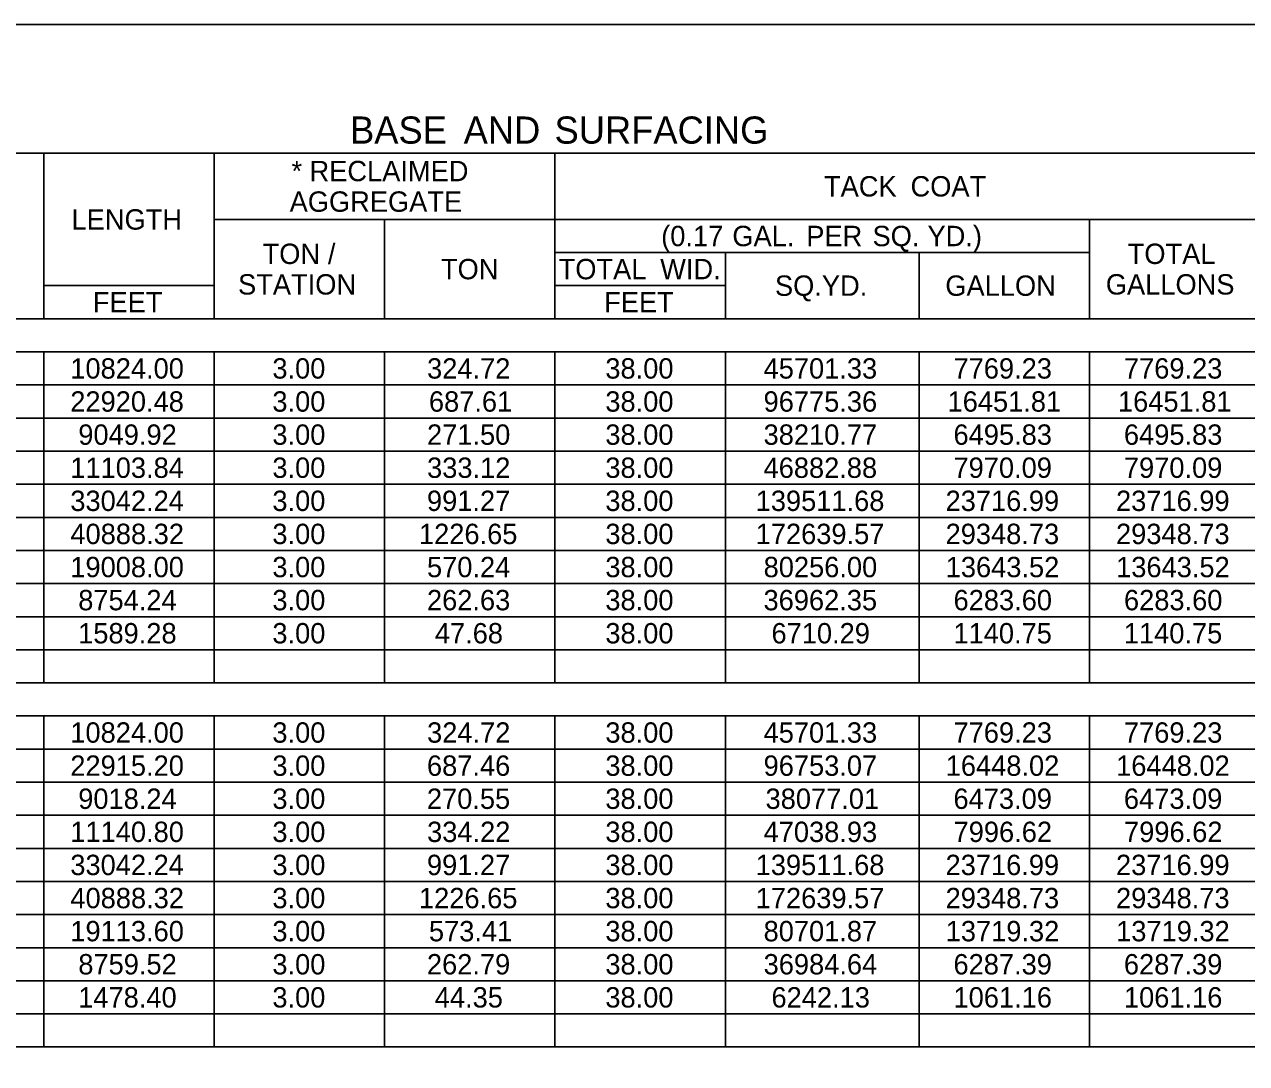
# Model space of a CAD drawing. Extents: x 2261867 to 2275370, y -3124789 to -3122260.
# Drawn here: x 2269764 to 2270088.1, y -3123898.7 to -3123623.2 of the extents above; entities that cross this region are included whole.
import ezdxf

# ---------------------------------------------------------------- set-up
doc = ezdxf.new("R2010")
doc.units = 0
doc.layers.add('Default', color=7, linetype='Continuous')
doc.layers.add('DSN_DRFT_Named-Boundary', color=7, linetype='Continuous')

msp = doc.modelspace()

# ---------------------------------------------------------------- linework, layer by layer
at = {"layer": 'Default'}
for p, q in [((2269400.16, -3123657.37), (2270414.11, -3123657.37)), ((2269769.15, -3123701.24), (2269769.15, -3123657.37)), ((2269814.34, -3123701.24), (2269814.34, -3123657.37)), ((2269904.72, -3123701.24), (2269904.72, -3123657.37)), ((2269814.34, -3123674.92), (2270414.11, -3123674.92)), ((2269859.53, -3123701.24), (2269859.53, -3123674.92)), ((2270046.44, -3123701.24), (2270046.44, -3123674.92)), ((2269904.72, -3123683.69), (2270046.44, -3123683.69)), ((2269949.92, -3123701.24), (2269949.92, -3123683.69)), ((2270001.25, -3123701.24), (2270001.25, -3123683.69)), ((2269769.15, -3123692.47), (2269814.34, -3123692.47)), ((2269814.34, -3123701.24), (2269814.34, -3123692.47)), ((2269904.72, -3123692.47), (2269949.92, -3123692.47)), ((2269949.92, -3123701.24), (2269949.92, -3123692.47)), ((2269400.16, -3123701.24), (2270414.11, -3123701.24)), ((2269814.34, -3123701.24), (2269949.92, -3123701.24)), ((2269949.92, -3123701.24), (2270001.25, -3123701.24)), ((2270001.25, -3123701.24), (2270136.82, -3123701.24)), ((2269400.16, -3123710.02), (2270414.11, -3123710.02)), ((2269769.15, -3123797.77), (2269769.15, -3123710.02)), ((2269769.15, -3123797.77), (2269769.15, -3123710.02)), ((2269814.34, -3123797.77), (2269814.34, -3123710.02)), ((2269814.34, -3123797.77), (2269814.34, -3123710.02)), ((2269859.53, -3123797.77), (2269859.53, -3123710.02)), ((2269859.53, -3123797.77), (2269859.53, -3123710.02)), ((2269904.72, -3123797.77), (2269904.72, -3123710.02)), ((2269904.72, -3123797.77), (2269904.72, -3123710.02)), ((2269949.92, -3123797.77), (2269949.92, -3123710.02)), ((2269949.92, -3123797.77), (2269949.92, -3123710.02)), ((2270001.25, -3123797.77), (2270001.25, -3123710.02)), ((2270001.25, -3123797.77), (2270001.25, -3123710.02)), ((2270046.44, -3123797.77), (2270046.44, -3123710.02)), ((2270046.44, -3123797.77), (2270046.44, -3123710.02)), ((2269400.16, -3123718.79), (2270414.11, -3123718.79)), ((2269400.16, -3123727.57), (2270414.11, -3123727.57)), ((2269400.16, -3123736.34), (2270414.11, -3123736.34)), ((2269400.16, -3123745.12), (2270414.11, -3123745.12)), ((2269400.16, -3123753.89), (2270414.11, -3123753.89)), ((2269400.16, -3123762.67), (2270414.11, -3123762.67)), ((2269400.16, -3123771.44), (2270414.11, -3123771.44)), ((2269400.16, -3123780.22), (2270414.11, -3123780.22)), ((2269400.16, -3123788.99), (2270414.11, -3123788.99)), ((2269400.16, -3123797.77), (2270414.11, -3123797.77)), ((2269400.16, -3123797.77), (2270414.11, -3123797.77)), ((2269400.16, -3123806.54), (2270414.11, -3123806.54)), ((2269769.15, -3123894.29), (2269769.15, -3123806.54)), ((2269769.15, -3123894.29), (2269769.15, -3123806.54)), ((2269814.34, -3123894.29), (2269814.34, -3123806.54)), ((2269814.34, -3123894.29), (2269814.34, -3123806.54)), ((2269859.53, -3123894.29), (2269859.53, -3123806.54)), ((2269859.53, -3123894.29), (2269859.53, -3123806.54)), ((2269904.72, -3123894.29), (2269904.72, -3123806.54)), ((2269904.72, -3123894.29), (2269904.72, -3123806.54)), ((2269949.92, -3123894.29), (2269949.92, -3123806.54)), ((2269949.92, -3123894.29), (2269949.92, -3123806.54)), ((2270001.25, -3123894.29), (2270001.25, -3123806.54)), ((2270001.25, -3123894.29), (2270001.25, -3123806.54)), ((2270046.44, -3123894.29), (2270046.44, -3123806.54)), ((2270046.44, -3123894.29), (2270046.44, -3123806.54)), ((2269400.16, -3123815.32), (2270414.11, -3123815.32)), ((2269400.16, -3123824.09), (2270414.11, -3123824.09)), ((2269400.16, -3123832.87), (2270414.11, -3123832.87)), ((2269400.16, -3123841.64), (2270414.11, -3123841.64)), ((2269400.16, -3123850.42), (2270414.11, -3123850.42)), ((2269400.16, -3123859.19), (2270414.11, -3123859.19)), ((2269400.16, -3123867.97), (2270414.11, -3123867.97)), ((2269400.16, -3123876.74), (2270414.11, -3123876.74)), ((2269400.16, -3123885.52), (2270414.11, -3123885.52)), ((2269400.16, -3123894.29), (2270414.11, -3123894.29)), ((2269400.16, -3123894.29), (2270414.11, -3123894.29))]:
    msp.add_line(p, q, dxfattribs=at)
at = {"layer": 'DSN_DRFT_Named-Boundary'}
msp.add_lwpolyline([(2269094.64, -3124789.38), (2270719.64, -3124789.38), (2270719.64, -3123623.23), (2269094.64, -3123623.23)], close=True, dxfattribs=at)

# ---------------------------------------------------------------- texts
at = {"layer": 'Default'}
for s, height, p in [('BASE', 7.2, (2269850.37, -3123654.83)), (' AND', 7.2, (2269877.82, -3123654.83)), (' SURFACING', 7.2, (2269901.92, -3123654.83)), ('*', 5.4, (2269834.86, -3123664.79)), (' RECLAIMED', 5.4, (2269837.63, -3123664.79)), ('TACK', 5.4, (2269976.05, -3123668.84)), (' COAT', 5.4, (2269996.99, -3123668.84)), ('AGGREGATE', 5.4, (2269834.36, -3123672.89)), ('LENGTH', 5.4, (2269776.53, -3123677.62)), ('(0.17', 5.4, (2269932.88, -3123682.01)), (' GAL.', 5.4, (2269949.74, -3123682.01)), (' PER', 5.4, (2269969.34, -3123682.01)), (' SQ.', 5.4, (2269986.91, -3123682.01)), (' YD.)', 5.4, (2270001.49, -3123682.01)), ('TON', 5.4, (2269827.18, -3123686.73)), (' /', 5.4, (2269842.5, -3123686.73)), ('TOTAL', 5.4, (2270056.58, -3123686.73)), ('TON', 5.4, (2269874.47, -3123690.78)), ('TOTAL', 5.4, (2269905.69, -3123690.78)), (' WID.', 5.4, (2269930.61, -3123690.78)), ('STATION', 5.4, (2269820.68, -3123694.83)), ('SQ.YD.', 5.4, (2269963.05, -3123695.17)), ('GALLON', 5.4, (2270008.22, -3123695.17)), ('GALLONS', 5.4, (2270050.78, -3123694.83)), ('FEET', 5.4, (2269782.18, -3123699.56)), ('FEET', 5.4, (2269917.75, -3123699.56)), ('10824.00', 5.4, (2269776.2, -3123717.11)), ('3.00', 5.4, (2269829.78, -3123717.11)), ('324.72', 5.4, (2269870.8, -3123717.11)), ('38.00', 5.4, (2269918.07, -3123717.11)), ('45701.33', 5.4, (2269960.03, -3123717.11)), ('7769.23', 5.4, (2270010.39, -3123717.11)), ('7769.23', 5.4, (2270055.58, -3123717.11)), ('22920.48', 5.4, (2269776.19, -3123725.88)), ('3.00', 5.4, (2269829.78, -3123725.88)), ('687.61', 5.4, (2269871.29, -3123725.88)), ('38.00', 5.4, (2269918.07, -3123725.88)), ('96775.36', 5.4, (2269960.03, -3123725.88)), ('16451.81', 5.4, (2270008.81, -3123725.88)), ('16451.81', 5.4, (2270054, -3123725.88)), ('9049.92', 5.4, (2269778.32, -3123734.66)), ('3.00', 5.4, (2269829.78, -3123734.66)), ('271.50', 5.4, (2269870.78, -3123734.66)), ('38.00', 5.4, (2269918.07, -3123734.66)), ('38210.77', 5.4, (2269960.03, -3123734.66)), ('6495.83', 5.4, (2270010.39, -3123734.66)), ('6495.83', 5.4, (2270055.58, -3123734.66)), ('11103.84', 5.4, (2269776.2, -3123743.43)), ('3.00', 5.4, (2269829.78, -3123743.43)), ('333.12', 5.4, (2269870.8, -3123743.43)), ('38.00', 5.4, (2269918.07, -3123743.43)), ('46882.88', 5.4, (2269960.02, -3123743.43)), ('7970.09', 5.4, (2270010.38, -3123743.43)), ('7970.09', 5.4, (2270055.57, -3123743.43)), ('33042.24', 5.4, (2269776.2, -3123752.21)), ('3.00', 5.4, (2269829.78, -3123752.21)), ('991.27', 5.4, (2269870.77, -3123752.21)), ('38.00', 5.4, (2269918.07, -3123752.21)), ('139511.68', 5.4, (2269957.93, -3123752.21)), ('23716.99', 5.4, (2270008.28, -3123752.21)), ('23716.99', 5.4, (2270053.48, -3123752.21)), ('40888.32', 5.4, (2269776.22, -3123760.98)), ('3.00', 5.4, (2269829.78, -3123760.98)), ('1226.65', 5.4, (2269868.65, -3123760.98)), ('38.00', 5.4, (2269918.07, -3123760.98)), ('172639.57', 5.4, (2269957.93, -3123760.98)), ('29348.73', 5.4, (2270008.29, -3123760.98)), ('29348.73', 5.4, (2270053.48, -3123760.98)), ('19008.00', 5.4, (2269776.2, -3123769.76)), ('3.00', 5.4, (2269829.78, -3123769.76)), ('570.24', 5.4, (2269870.78, -3123769.76)), ('38.00', 5.4, (2269918.07, -3123769.76)), ('80256.00', 5.4, (2269960.04, -3123769.76)), ('13643.52', 5.4, (2270008.32, -3123769.76)), ('13643.52', 5.4, (2270053.51, -3123769.76)), ('8754.24', 5.4, (2269778.3, -3123778.53)), ('3.00', 5.4, (2269829.78, -3123778.53)), ('262.63', 5.4, (2269870.77, -3123778.53)), ('38.00', 5.4, (2269918.07, -3123778.53)), ('36962.35', 5.4, (2269960.01, -3123778.53)), ('6283.60', 5.4, (2270010.4, -3123778.53)), ('6283.60', 5.4, (2270055.59, -3123778.53)), ('1589.28', 5.4, (2269778.28, -3123787.31)), ('3.00', 5.4, (2269829.78, -3123787.31)), ('47.68', 5.4, (2269872.86, -3123787.31)), ('38.00', 5.4, (2269918.07, -3123787.31)), ('6710.29', 5.4, (2269962.12, -3123787.31)), ('1140.75', 5.4, (2270010.37, -3123787.31)), ('1140.75', 5.4, (2270055.56, -3123787.31)), ('10824.00', 5.4, (2269776.2, -3123813.63)), ('3.00', 5.4, (2269829.78, -3123813.63)), ('324.72', 5.4, (2269870.8, -3123813.63)), ('38.00', 5.4, (2269918.07, -3123813.63)), ('45701.33', 5.4, (2269960.03, -3123813.63)), ('7769.23', 5.4, (2270010.39, -3123813.63)), ('7769.23', 5.4, (2270055.58, -3123813.63)), ('22915.20', 5.4, (2269776.2, -3123822.41)), ('3.00', 5.4, (2269829.78, -3123822.41)), ('687.46', 5.4, (2269870.77, -3123822.41)), ('38.00', 5.4, (2269918.07, -3123822.41)), ('96753.07', 5.4, (2269960.03, -3123822.41)), ('16448.02', 5.4, (2270008.32, -3123822.41)), ('16448.02', 5.4, (2270053.51, -3123822.41)), ('9018.24', 5.4, (2269778.3, -3123831.18)), ('3.00', 5.4, (2269829.78, -3123831.18)), ('270.55', 5.4, (2269870.75, -3123831.18)), ('38.00', 5.4, (2269918.07, -3123831.18)), ('38077.01', 5.4, (2269960.55, -3123831.18)), ('6473.09', 5.4, (2270010.38, -3123831.18)), ('6473.09', 5.4, (2270055.57, -3123831.18)), ('11140.80', 5.4, (2269776.2, -3123839.96)), ('3.00', 5.4, (2269829.78, -3123839.96)), ('334.22', 5.4, (2269870.8, -3123839.96)), ('38.00', 5.4, (2269918.07, -3123839.96)), ('47038.93', 5.4, (2269960.03, -3123839.96)), ('7996.62', 5.4, (2270010.41, -3123839.96)), ('7996.62', 5.4, (2270055.61, -3123839.96)), ('33042.24', 5.4, (2269776.2, -3123848.73)), ('3.00', 5.4, (2269829.78, -3123848.73)), ('991.27', 5.4, (2269870.77, -3123848.73)), ('38.00', 5.4, (2269918.07, -3123848.73)), ('139511.68', 5.4, (2269957.93, -3123848.73)), ('23716.99', 5.4, (2270008.28, -3123848.73)), ('23716.99', 5.4, (2270053.48, -3123848.73)), ('40888.32', 5.4, (2269776.22, -3123857.51)), ('3.00', 5.4, (2269829.78, -3123857.51)), ('1226.65', 5.4, (2269868.65, -3123857.51)), ('38.00', 5.4, (2269918.07, -3123857.51)), ('172639.57', 5.4, (2269957.93, -3123857.51)), ('29348.73', 5.4, (2270008.29, -3123857.51)), ('29348.73', 5.4, (2270053.48, -3123857.51)), ('19113.60', 5.4, (2269776.2, -3123866.28)), ('3.00', 5.4, (2269829.78, -3123866.28)), ('573.41', 5.4, (2269871.29, -3123866.28)), ('38.00', 5.4, (2269918.07, -3123866.28)), ('80701.87', 5.4, (2269960.03, -3123866.28)), ('13719.32', 5.4, (2270008.32, -3123866.28)), ('13719.32', 5.4, (2270053.51, -3123866.28)), ('8759.52', 5.4, (2269778.32, -3123875.06)), ('3.00', 5.4, (2269829.78, -3123875.06)), ('262.79', 5.4, (2269870.76, -3123875.06)), ('38.00', 5.4, (2269918.07, -3123875.06)), ('36984.64', 5.4, (2269960.04, -3123875.06)), ('6287.39', 5.4, (2270010.38, -3123875.06)), ('6287.39', 5.4, (2270055.57, -3123875.06)), ('1478.40', 5.4, (2269778.3, -3123883.83)), ('3.00', 5.4, (2269829.78, -3123883.83)), ('44.35', 5.4, (2269872.84, -3123883.83)), ('38.00', 5.4, (2269918.07, -3123883.83)), ('6242.13', 5.4, (2269962.12, -3123883.83)), ('1061.16', 5.4, (2270010.39, -3123883.83)), ('1061.16', 5.4, (2270055.58, -3123883.83))]:
    msp.add_text(s, height=height, dxfattribs=at).set_placement(p)

doc.saveas('drawing.dxf')
